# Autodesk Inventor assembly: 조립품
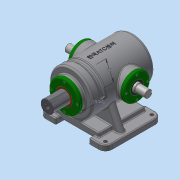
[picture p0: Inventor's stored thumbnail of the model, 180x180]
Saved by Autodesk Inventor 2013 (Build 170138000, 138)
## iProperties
Created: 2018-06
Part Number: 조립품
Document SubType Name: Assembly
Designer: Administrator
Author: Administrator
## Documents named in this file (13)
- C:\Users\Administrator\Desktop\380628V1001\조립품.iam
- C:\Users\Administrator\Desktop\380628V1001\본체.ipt
- C:\Users\Administrator\Desktop\380628V1001\가변스프링.ipt
- C:\Users\Administrator\Desktop\380628V1001\베어링 6205.ipt
- 베어링 6205.ipt
- C:\Users\Administrator\Desktop\380628V1001\볼트 M4.ipt
- C:\Users\Administrator\Desktop\380628V1001\부시.ipt
- C:\Users\Administrator\Desktop\380628V1001\슬라이드 커버.ipt
- C:\Users\Administrator\Desktop\380628V1001\슬라이드.ipt
- C:\Users\Administrator\Desktop\380628V1001\오일실.ipt
- 오일실.ipt
- C:\Users\Administrator\Desktop\380628V1001\축 커버.ipt
- C:\Users\Administrator\Desktop\380628V1001\편심축.ipt
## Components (1 placed, 1 different names)
1. 가변스프링:1
